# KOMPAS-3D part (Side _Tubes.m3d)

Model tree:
1. Plane XY
2. Plane ZX
3. Plane ZY
4. X Axis
5. Y Axis
6. Z Axis
7. Origin
8. Sketch:1
9. Extrude:1
     Wall Thickness 1 = 1; Wall Thickness 2 = 10; Distance 1 = 2000; Distance 2 = 3980

Referenced files in D:\Documents and Settings\kashirsky\Рабочий стол\Cottage\: Cottage.a3d
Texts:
  Steel DIN 17102
  Three Point Plane
  Plane at Angle
  Line and Point Plane
  Axis through Two Vertices
  Axis of Feature
  Axis of Conical Surface
  Axis through Edge
  Trim by Surface
  Trim by Sketch
  Feature with No History
  Intersection Axis of Two Planes
  Two Line Plane
  Line and Face Plane
  Bend by line
  Hole in sheet body
  Cut in sheet body
  Point in CM
  Linear Dimension from Line to Point
  Surface Finish Symbol
  Geometric Tolerance Symbol
  Leader #1
  Leader #2
  Leader #3
  Shape Deviations and Datum
  Node point number
  Mark of coordination axis
  Node point designation
  Mark/Reference designation with leader
  Mark/reference designation on line
  Mark/Reference designation without leader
